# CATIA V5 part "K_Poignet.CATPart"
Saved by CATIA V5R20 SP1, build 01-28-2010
Part number: pignet
Bounding box of the stored display mesh (mm): x -5 to 5, y -4.99 to 50.767, z -75.757 to 0
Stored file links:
  G:\Khaled_CFAO_2011\SIL\SIL_GR1\mroland\Khaled\CAD_CATIA_Modifie\K_Poignet.CATPart
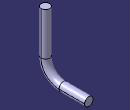
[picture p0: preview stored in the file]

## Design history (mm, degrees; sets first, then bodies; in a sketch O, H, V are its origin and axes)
Set1
  Sketch1 on xy-plane, origin (0, 0, 0), H (1, 0, 0), V (0, 1, 0)
    circle A1 centre (0, 0) radius 5
    point P1 (0, 0)
    radius A1 = 5
    coincidence: P1 O
Body1 (main body)
  Sketch2 on yz-plane, origin (0, 0, 0), H (0, 1, 0), V (0, 0, 1)
    point P1 (4.7666, 0)
    line L1 (4.7666, 0) -> (4.7666, -50)
    line L2 (20.7666, -66) -> (50.7666, -66)
    arc A1 centre (20.7666, -50) radius 16 from (4.7666, -50) to (20.7666, -66) ccw
    radius A1 = 16
    length L1 = 50
    length L2 = 30
    coincidence: P1 H
    vertical: L1 V
    horizontal: L2 H
    tangency: A1 L1, A1 L2
  Rib1: profile Sketch1, centre curve Sketch2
